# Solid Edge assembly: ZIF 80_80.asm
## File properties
Title: Zylinder
Author: bmolnar
Template: iso metric assembly.asm
Last saved by: psaghy
Revision: 27
Application: Solid Edge
Username: bmolnar
Dokumentum tartalom típus: 1
Document Number: ZIF 80/80
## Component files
Kolbenstange.par
Kit_1.par
Kit_2.par
Profilrohr.par
Mutter.par
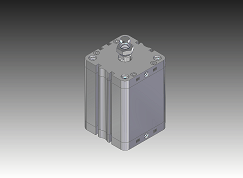
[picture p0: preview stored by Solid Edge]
